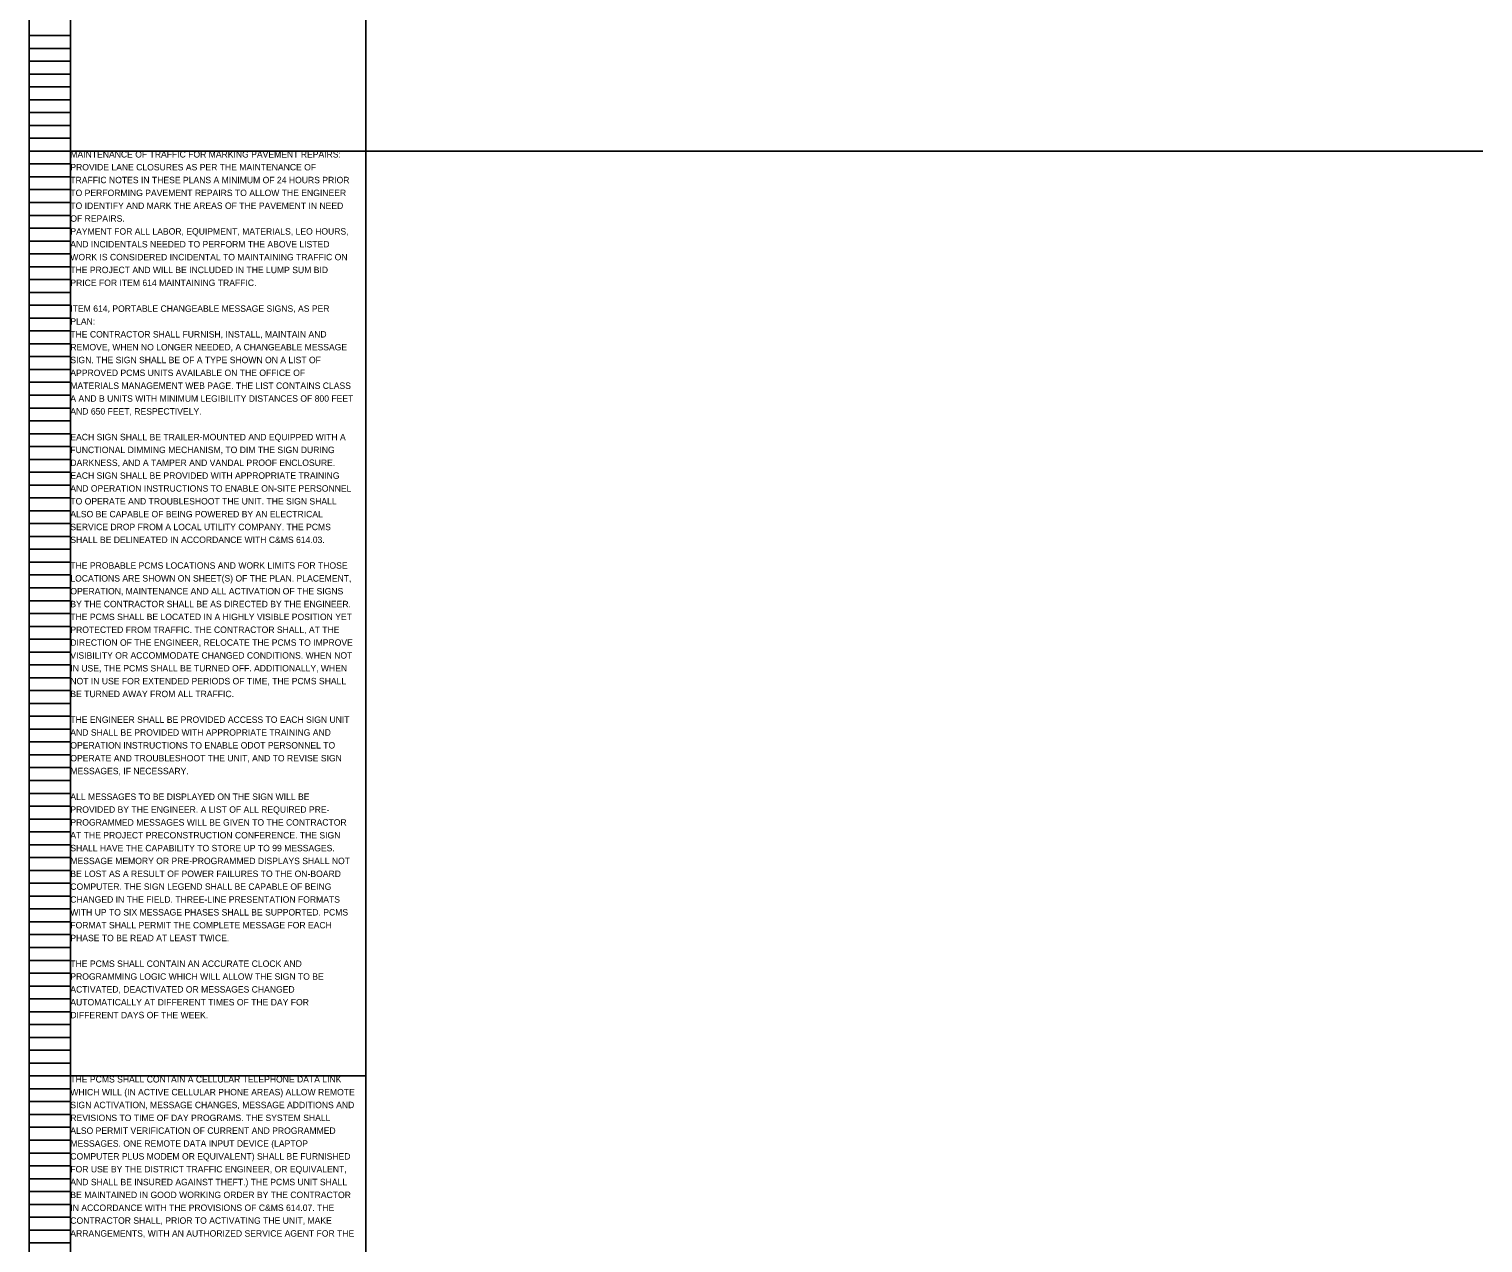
# Model space of a CAD drawing. Extents: x 16463 to 16500, y 5400 to 5823.
# Drawn here: x 16463.05 to 16494.74, y 5638.39 to 5664.85 of the extents above; entities that cross this region are included whole.
import ezdxf

# ---------------------------------------------------------------- set-up
doc = ezdxf.new("R2010")
doc.units = 0
for name, color, linetype in [('SC_Scratch1', 7, 'Continuous'), ('SH_Data', 7, 'Continuous'), ('SH_Text', 7, 'Continuous')]:
    doc.layers.add(name, color=color, linetype=linetype)

msp = doc.modelspace()

# ---------------------------------------------------------------- linework, layer by layer
at = {"layer": 'SC_Scratch1'}
msp.add_line((16470.389, 5662.192), (16494.742, 5662.192), dxfattribs=at)
for points in [[(16463.949, 5682.352), (16470.389, 5682.352), (16470.389, 5662.192), (16463.949, 5662.192)], [(16463.949, 5662.192), (16470.389, 5662.192), (16470.389, 5642.032), (16463.949, 5642.032)], [(16463.949, 5642.032), (16470.389, 5642.032), (16470.389, 5621.872), (16463.949, 5621.872)]]:
    msp.add_lwpolyline(points, close=True, dxfattribs=at)
at = {"layer": 'SH_Data'}
for p, q in [((16463.049, 5662.192), (16463.049, 5682.352)), ((16463.949, 5662.192), (16463.949, 5682.352)), ((16463.049, 5664.712), (16463.949, 5664.712)), ((16463.049, 5664.432), (16463.949, 5664.432)), ((16463.049, 5664.152), (16463.949, 5664.152)), ((16463.049, 5663.872), (16463.949, 5663.872)), ((16463.049, 5663.592), (16463.949, 5663.592)), ((16463.049, 5663.312), (16463.949, 5663.312)), ((16463.049, 5663.032), (16463.949, 5663.032)), ((16463.049, 5662.752), (16463.949, 5662.752)), ((16463.049, 5662.472), (16463.949, 5662.472)), ((16463.049, 5642.032), (16463.049, 5662.192)), ((16463.049, 5662.192), (16463.949, 5662.192)), ((16463.049, 5662.192), (16463.949, 5662.192)), ((16463.949, 5642.032), (16463.949, 5662.192)), ((16463.049, 5661.912), (16463.949, 5661.912)), ((16463.049, 5661.632), (16463.949, 5661.632)), ((16463.049, 5661.352), (16463.949, 5661.352)), ((16463.049, 5661.072), (16463.949, 5661.072)), ((16463.049, 5660.792), (16463.949, 5660.792)), ((16463.049, 5660.512), (16463.949, 5660.512)), ((16463.049, 5660.232), (16463.949, 5660.232)), ((16463.049, 5659.952), (16463.949, 5659.952)), ((16463.049, 5659.672), (16463.949, 5659.672)), ((16463.049, 5659.392), (16463.949, 5659.392)), ((16463.049, 5659.112), (16463.949, 5659.112)), ((16463.049, 5658.832), (16463.949, 5658.832)), ((16463.049, 5658.552), (16463.949, 5658.552)), ((16463.049, 5658.272), (16463.949, 5658.272)), ((16463.049, 5657.992), (16463.949, 5657.992)), ((16463.049, 5657.712), (16463.949, 5657.712)), ((16463.049, 5657.432), (16463.949, 5657.432)), ((16463.049, 5657.152), (16463.949, 5657.152)), ((16463.049, 5656.872), (16463.949, 5656.872)), ((16463.049, 5656.592), (16463.949, 5656.592)), ((16463.049, 5656.312), (16463.949, 5656.312)), ((16463.049, 5656.032), (16463.949, 5656.032)), ((16463.049, 5655.752), (16463.949, 5655.752)), ((16463.049, 5655.472), (16463.949, 5655.472)), ((16463.049, 5655.192), (16463.949, 5655.192)), ((16463.049, 5654.912), (16463.949, 5654.912)), ((16463.049, 5654.632), (16463.949, 5654.632)), ((16463.049, 5654.352), (16463.949, 5654.352)), ((16463.049, 5654.072), (16463.949, 5654.072)), ((16463.049, 5653.792), (16463.949, 5653.792)), ((16463.049, 5653.512), (16463.949, 5653.512)), ((16463.049, 5653.232), (16463.949, 5653.232)), ((16463.049, 5652.952), (16463.949, 5652.952)), ((16463.049, 5652.672), (16463.949, 5652.672)), ((16463.049, 5652.392), (16463.949, 5652.392)), ((16463.049, 5652.112), (16463.949, 5652.112)), ((16463.049, 5651.832), (16463.949, 5651.832)), ((16463.049, 5651.552), (16463.949, 5651.552)), ((16463.049, 5651.272), (16463.949, 5651.272)), ((16463.049, 5650.992), (16463.949, 5650.992)), ((16463.049, 5650.712), (16463.949, 5650.712)), ((16463.049, 5650.432), (16463.949, 5650.432)), ((16463.049, 5650.152), (16463.949, 5650.152)), ((16463.049, 5649.872), (16463.949, 5649.872)), ((16463.049, 5649.592), (16463.949, 5649.592)), ((16463.049, 5649.312), (16463.949, 5649.312)), ((16463.049, 5649.032), (16463.949, 5649.032)), ((16463.049, 5648.752), (16463.949, 5648.752)), ((16463.049, 5648.472), (16463.949, 5648.472)), ((16463.049, 5648.192), (16463.949, 5648.192)), ((16463.049, 5647.912), (16463.949, 5647.912)), ((16463.049, 5647.632), (16463.949, 5647.632)), ((16463.049, 5647.352), (16463.949, 5647.352)), ((16463.049, 5647.072), (16463.949, 5647.072)), ((16463.049, 5646.792), (16463.949, 5646.792)), ((16463.049, 5646.512), (16463.949, 5646.512)), ((16463.049, 5646.232), (16463.949, 5646.232)), ((16463.049, 5645.952), (16463.949, 5645.952)), ((16463.049, 5645.672), (16463.949, 5645.672)), ((16463.049, 5645.392), (16463.949, 5645.392)), ((16463.049, 5645.112), (16463.949, 5645.112)), ((16463.049, 5644.832), (16463.949, 5644.832)), ((16463.049, 5644.552), (16463.949, 5644.552)), ((16463.049, 5644.272), (16463.949, 5644.272)), ((16463.049, 5643.992), (16463.949, 5643.992)), ((16463.049, 5643.712), (16463.949, 5643.712)), ((16463.049, 5643.432), (16463.949, 5643.432)), ((16463.049, 5643.152), (16463.949, 5643.152)), ((16463.049, 5642.872), (16463.949, 5642.872)), ((16463.049, 5642.592), (16463.949, 5642.592)), ((16463.049, 5642.312), (16463.949, 5642.312)), ((16463.049, 5621.872), (16463.049, 5642.032)), ((16463.049, 5642.032), (16463.949, 5642.032)), ((16463.049, 5642.032), (16463.949, 5642.032)), ((16463.949, 5621.872), (16463.949, 5642.032)), ((16463.049, 5641.752), (16463.949, 5641.752)), ((16463.049, 5641.472), (16463.949, 5641.472)), ((16463.049, 5641.192), (16463.949, 5641.192)), ((16463.049, 5640.912), (16463.949, 5640.912)), ((16463.049, 5640.632), (16463.949, 5640.632)), ((16463.049, 5640.352), (16463.949, 5640.352)), ((16463.049, 5640.072), (16463.949, 5640.072)), ((16463.049, 5639.792), (16463.949, 5639.792)), ((16463.049, 5639.512), (16463.949, 5639.512)), ((16463.049, 5639.232), (16463.949, 5639.232)), ((16463.049, 5638.952), (16463.949, 5638.952)), ((16463.049, 5638.672), (16463.949, 5638.672)), ((16463.049, 5638.392), (16463.949, 5638.392))]:
    msp.add_line(p, q, dxfattribs=at)

# ---------------------------------------------------------------- texts
at = {"layer": 'SH_Text'}
for s, p in [('MAINTENANCE OF TRAFFIC FOR MARKING PAVEMENT REPAIRS:', (16463.949, 5662.052)), ('PROVIDE LANE CLOSURES AS PER THE MAINTENANCE OF ', (16463.949, 5661.772)), ('TRAFFIC NOTES IN THESE PLANS A MINIMUM OF 24 HOURS PRIOR ', (16463.949, 5661.492)), ('TO PERFORMING PAVEMENT REPAIRS TO ALLOW THE ENGINEER ', (16463.949, 5661.212)), ('TO IDENTIFY AND MARK THE AREAS OF THE PAVEMENT IN NEED ', (16463.949, 5660.932)), ('OF REPAIRS.', (16463.949, 5660.652)), ('PAYMENT FOR ALL LABOR, EQUIPMENT, MATERIALS, LEO HOURS, ', (16463.949, 5660.372)), ('AND INCIDENTALS NEEDED TO PERFORM THE ABOVE LISTED ', (16463.949, 5660.092)), ('WORK IS CONSIDERED INCIDENTAL TO MAINTAINING TRAFFIC ON ', (16463.949, 5659.812)), ('THE PROJECT AND WILL BE INCLUDED IN THE LUMP SUM BID ', (16463.949, 5659.532)), ('PRICE FOR ITEM 614 MAINTAINING TRAFFIC.', (16463.949, 5659.252)), ('ITEM 614, PORTABLE CHANGEABLE MESSAGE SIGNS, AS PER ', (16463.949, 5658.689)), ('PLAN:', (16463.949, 5658.409)), ('THE CONTRACTOR SHALL FURNISH, INSTALL, MAINTAIN AND ', (16463.949, 5658.129)), ('REMOVE, WHEN NO LONGER NEEDED, A CHANGEABLE MESSAGE ', (16463.949, 5657.849)), ('APPROVED PCMS UNITS AVAILABLE ON THE OFFICE OF ', (16463.949, 5657.289)), ('SIGN. THE SIGN SHALL BE OF A TYPE SHOWN ON A LIST OF ', (16463.949, 5657.569)), ('MATERIALS MANAGEMENT WEB PAGE. THE LIST CONTAINS CLASS ', (16463.949, 5657.009)), ('A AND B UNITS WITH MINIMUM LEGIBILITY DISTANCES OF 800 FEET ', (16463.949, 5656.729)), ('AND 650 FEET, RESPECTIVELY. ', (16463.949, 5656.449)), ('EACH SIGN SHALL BE TRAILER-MOUNTED AND EQUIPPED WITH A ', (16463.949, 5655.889)), ('FUNCTIONAL DIMMING MECHANISM, TO DIM THE SIGN DURING ', (16463.949, 5655.609)), ('DARKNESS, AND A TAMPER AND VANDAL PROOF ENCLOSURE. ', (16463.949, 5655.329)), ('EACH SIGN SHALL BE PROVIDED WITH APPROPRIATE TRAINING ', (16463.949, 5655.049)), ('AND OPERATION INSTRUCTIONS TO ENABLE ON-SITE PERSONNEL ', (16463.949, 5654.769)), ('TO OPERATE AND TROUBLESHOOT THE UNIT. THE SIGN SHALL ', (16463.949, 5654.489)), ('ALSO BE CAPABLE OF BEING POWERED BY AN ELECTRICAL ', (16463.949, 5654.209)), ('SERVICE DROP FROM A LOCAL UTILITY COMPANY. THE PCMS ', (16463.949, 5653.929)), ('SHALL BE DELINEATED IN ACCORDANCE WITH C&MS 614.03. ', (16463.949, 5653.649)), ('THE PROBABLE PCMS LOCATIONS AND WORK LIMITS FOR THOSE ', (16463.949, 5653.089)), ('OPERATION, MAINTENANCE AND ALL ACTIVATION OF THE SIGNS ', (16463.949, 5652.529)), ('LOCATIONS ARE SHOWN ON SHEET(S) OF THE PLAN. PLACEMENT, ', (16463.949, 5652.809)), ('BY THE CONTRACTOR SHALL BE AS DIRECTED BY THE ENGINEER. ', (16463.949, 5652.249)), ('THE PCMS SHALL BE LOCATED IN A HIGHLY VISIBLE POSITION YET ', (16463.949, 5651.969)), ('PROTECTED FROM TRAFFIC. THE CONTRACTOR SHALL, AT THE ', (16463.949, 5651.689)), ('DIRECTION OF THE ENGINEER, RELOCATE THE PCMS TO IMPROVE ', (16463.949, 5651.409)), ('VISIBILITY OR ACCOMMODATE CHANGED CONDITIONS. WHEN NOT ', (16463.949, 5651.129)), ('IN USE, THE PCMS SHALL BE TURNED OFF. ADDITIONALLY, WHEN ', (16463.949, 5650.849)), ('NOT IN USE FOR EXTENDED PERIODS OF TIME, THE PCMS SHALL ', (16463.949, 5650.569)), ('BE TURNED AWAY FROM ALL TRAFFIC. ', (16463.949, 5650.289)), ('THE ENGINEER SHALL BE PROVIDED ACCESS TO EACH SIGN UNIT ', (16463.949, 5649.729)), ('AND SHALL BE PROVIDED WITH APPROPRIATE TRAINING AND ', (16463.949, 5649.449)), ('OPERATION INSTRUCTIONS TO ENABLE ODOT PERSONNEL TO ', (16463.949, 5649.169)), ('OPERATE AND TROUBLESHOOT THE UNIT, AND TO REVISE SIGN ', (16463.949, 5648.889)), ('MESSAGES, IF NECESSARY.', (16463.949, 5648.609)), ('ALL MESSAGES TO BE DISPLAYED ON THE SIGN WILL BE ', (16463.949, 5648.049)), ('PROVIDED BY THE ENGINEER. A LIST OF ALL REQUIRED PRE-', (16463.949, 5647.769)), ('PROGRAMMED MESSAGES WILL BE GIVEN TO THE CONTRACTOR ', (16463.949, 5647.489)), ('AT THE PROJECT PRECONSTRUCTION CONFERENCE. THE SIGN ', (16463.949, 5647.209)), ('SHALL HAVE THE CAPABILITY TO STORE UP TO 99 MESSAGES. ', (16463.949, 5646.929)), ('MESSAGE MEMORY OR PRE-PROGRAMMED DISPLAYS SHALL NOT ', (16463.949, 5646.649)), ('BE LOST AS A RESULT OF POWER FAILURES TO THE ON-BOARD ', (16463.949, 5646.369)), ('COMPUTER. THE SIGN LEGEND SHALL BE CAPABLE OF BEING ', (16463.949, 5646.089)), ('CHANGED IN THE FIELD. THREE-LINE PRESENTATION FORMATS ', (16463.949, 5645.809)), ('WITH UP TO SIX MESSAGE PHASES SHALL BE SUPPORTED. PCMS ', (16463.949, 5645.529)), ('FORMAT SHALL PERMIT THE COMPLETE MESSAGE FOR EACH ', (16463.949, 5645.249)), ('PHASE TO BE READ AT LEAST TWICE. ', (16463.949, 5644.969)), ('THE PCMS SHALL CONTAIN AN ACCURATE CLOCK AND ', (16463.949, 5644.409)), ('PROGRAMMING LOGIC WHICH WILL ALLOW THE SIGN TO BE ', (16463.949, 5644.129)), ('ACTIVATED, DEACTIVATED OR MESSAGES CHANGED ', (16463.949, 5643.849)), ('AUTOMATICALLY AT DIFFERENT TIMES OF THE DAY FOR ', (16463.949, 5643.569)), ('DIFFERENT DAYS OF THE WEEK.', (16463.949, 5643.289)), ('THE PCMS SHALL CONTAIN A CELLULAR TELEPHONE DATA LINK ', (16463.949, 5641.889)), ('WHICH WILL (IN ACTIVE CELLULAR PHONE AREAS) ALLOW REMOTE ', (16463.949, 5641.609)), ('SIGN ACTIVATION, MESSAGE CHANGES, MESSAGE ADDITIONS AND ', (16463.949, 5641.329)), ('REVISIONS TO TIME OF DAY PROGRAMS. THE SYSTEM SHALL ', (16463.949, 5641.049)), ('ALSO PERMIT VERIFICATION OF CURRENT AND PROGRAMMED ', (16463.949, 5640.769)), ('MESSAGES. ONE REMOTE DATA INPUT DEVICE (LAPTOP ', (16463.949, 5640.489)), ('COMPUTER PLUS MODEM OR EQUIVALENT) SHALL BE FURNISHED ', (16463.949, 5640.209)), ('FOR USE BY THE DISTRICT TRAFFIC ENGINEER, OR EQUIVALENT, ', (16463.949, 5639.929)), ('AND SHALL BE INSURED AGAINST THEFT.) THE PCMS UNIT SHALL ', (16463.949, 5639.649)), ('BE MAINTAINED IN GOOD WORKING ORDER BY THE CONTRACTOR ', (16463.949, 5639.369)), ('IN ACCORDANCE WITH THE PROVISIONS OF C&MS 614.07. THE ', (16463.949, 5639.089)), ('CONTRACTOR SHALL, PRIOR TO ACTIVATING THE UNIT, MAKE ', (16463.949, 5638.809)), ('ARRANGEMENTS, WITH AN AUTHORIZED SERVICE AGENT FOR THE ', (16463.949, 5638.529))]:
    msp.add_text(s, height=0.14, dxfattribs=at).set_placement(p)

doc.saveas('drawing.dxf')
